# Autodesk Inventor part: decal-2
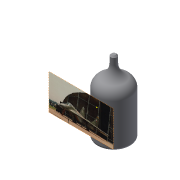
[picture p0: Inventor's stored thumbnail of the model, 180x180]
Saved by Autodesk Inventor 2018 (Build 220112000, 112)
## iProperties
Shininess: 64.0
Length Units: 11269
Angle Units: 11279
Time Units: 11290
Mass Units: 11283
Length Display Precision: 3
Angle Display Precision: 2
Compacted: True
Part Number: decal-2
Document SubType Name: Modeling
Created: 2002-12
Designer: deepak
Material: Generic
Density: 1 g/cm^3
Appearance: Default
Density: 0.0
Volumn: 0.0
Area: 0.0
PropertySet Name: Model Information
Control State: 0
Master: False
Checked Out: False
Author: deepak
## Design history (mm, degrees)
node "Sketch1"
sketch "Sketch2"
  geometry: L1 (2.054, 26.655)-(2.054, 21.177); L2 (11.64, 6.114)-(11.64, -24.209); L3 (11.64, -24.209)-(-0.098, -24.209); L4 (-0.098, -24.209)-(-0.098, 26.655); L5 (-0.098, 26.655)-(2.054, 26.655); A1 r 9.502 centre (11.556, 21.177) between (2.054, 21.177) and (7.532, 12.57); A2 r 7.127 centre (4.514, 6.114) between (11.64, 6.114) and (7.532, 12.57)
  constraints: 10 end point, 4 point on circle, 3 parallel, 3 tangent, 2 centre point, 1 perpendicular, 1 vertical
revolve "Revolution1" sketch "Sketch2" stored, may be unused: angle "d0" = 90 deg
fillet "Fillet1" dims "d1" = 2
chamfer "Chamfer1" distance "d2" = 1; stored, may be unused: second distance "d3" = 2, angle "d21" = 45 deg
workplane "Work Plane4"
sketch "Sketch7"
  geometry: L1 (-11.326, 14.075)-(33.849, 14.075); L2 (33.849, 14.075)-(33.849, -10.781); L3 (33.849, -10.781)-(-11.326, -10.781); L4 (-11.326, -10.781)-(-11.326, 14.075); 1 further point; 1 other entity
  constraints: 2 other
  node "Image6"
body "Solid1"
